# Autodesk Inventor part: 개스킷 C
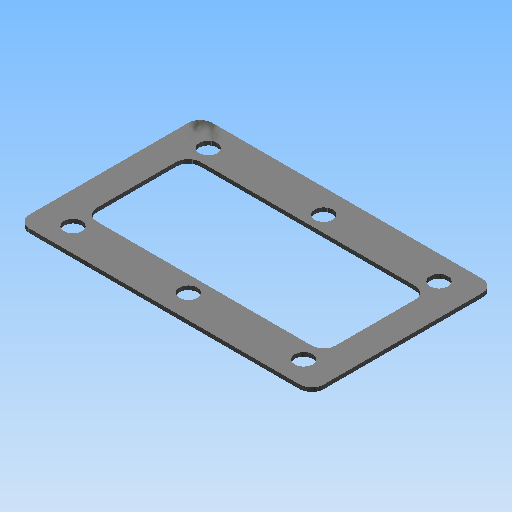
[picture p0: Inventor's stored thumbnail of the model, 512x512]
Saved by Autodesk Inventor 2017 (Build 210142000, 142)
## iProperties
Created: 2020-04
Part Number: 개스킷 C
Material: 고무
Document SubType Name: Modeling
Designer: mduedu
Density: 0.93 g/cm^3
Mass: 1.62617 g
Surface Area: 39.8367 cm^2
Volume: 1.74857 cm^3
Appearance: 고무 - 검은색 - 버전 1.1
Author: mduedu
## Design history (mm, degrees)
sketch "스케치1"
  geometry: L1 (37, 23)-(-37, 23); L2 (-37, 23)-(-37, -23); L3 (-37, -23)-(37, -23); L4 (37, -23)-(37, 23); L5 (37, 23)-(-37, -23); L6 (-37, 23)-(37, -23); L7 (30, 13)-(-30, 13); L8 (-30, 13)-(-30, -13); L9 (-30, -13)-(30, -13); L10 (30, -13)-(30, 13); L11 (30, 13)-(-30, -13); L12 (-30, 13)-(30, -13); 1 further point
  constraints: 24 end point, 4 midpoint, 4 parallel, 2 horizontal, 2 perpendicular
  dimensions: "d0" = 74 distance of L3.end L2.end; "d1" = 46 distance of L2.end L1.end; "d2" = 60 distance of L9.end L8.end; "d3" = 26 distance of L8.end L7.end
extrude "돌출1" new body sketch "스케치1" distance "d4" = 1; taper "d5" = 0 deg
fillet "모깎기1" dims "d6" = 3
fillet "모깎기2" dims "d7" = 3
sketch "스케치2"
  geometry: L1 (-29, -17)-(29, -17); L2 (29, -17)-(29, 17); L3 (29, 17)-(-29, 17); L4 (-29, 17)-(-29, -17); L5 (-29, -17)-(29, 17); L6 (29, -17)-(-29, 17); 7 further points
  constraints: 12 end point, 4 coincident, 4 midpoint, 2 parallel, 1 horizontal, 1 perpendicular
  dimensions: "d8" = 58 distance of L3.end L2.end; "d9" = 34 distance of L2.end L1.end
hole "구멍1" sketch "스케치2" at (-29, 17), (29, 17), (29, -17), (-29, -17), (0, 17), (0, -17) diameter "d10" = 4.5; stored, may be unused: countersink angle "d14" = 90 deg, drill point angle "d16" = 118 deg; dims "d11" = 6, "d12" = 4, "d13" = 2, "d15" = 8
node "솔리드1"
